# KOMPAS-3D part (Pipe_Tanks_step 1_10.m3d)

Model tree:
1. X Axis
2. Y Axis
3. Z Axis  (labels: Bend 90 Dn 50; Pipe Dn 50; C:\Program Files\ASCON\KOMPAS-3D V10\Sys\graphic.lyt; Pipe_Tanks_step 1_10.m3d)
     Òîëùèíà ñòåíêè 1 = 1

Referenced files in C:\Documents and Settings\kashirsky\Мои документы\Camtasia Studio\Pipelines3D\Tanks\: Tanks_step 1.a3d, Tanks_step 1.spw
Referenced files in C:\Documents and Settings\kashirsky\Мои документы\Camtasia Studio\Pipelines3D\Tanks\Tanks_step 1_Pipes\: Pipe_Tanks_step 1_10.m3d
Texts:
  Pipe Dn 50
  Steel ASTM A295
  Three Point Plane
  Plane at Angle
  Line and Point Plane
  Axis through Two Vertices
  Axis of Feature
  Axis of Conical Surface
  Axis through Edge
  Trim by Surface
  Trim by Sketch
  Feature with No History
  Intersection Axis of Two Planes
  Two Line Plane
  Line and Face Plane
  Bend by line
  Hole in sheet body
  Cut in sheet body
  Point in CM
  Linear Dimension from Line to Point
  Surface Finish Symbol
  Geometric Tolerance Symbol
  Leader #1
  Leader #2
  Leader #3
  Shape Deviations and Datum
  Node point number
  Mark of coordination axis
  Node point designation
  Mark/Reference designation with leader
  Mark/reference designation on line
  Mark/Reference designation without leader
  Bend 90 Dn 50
  Plane of section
